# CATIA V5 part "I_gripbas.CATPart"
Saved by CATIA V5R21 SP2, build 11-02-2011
Part number: I_gripbas
Bounding box of the stored display mesh (mm): x -50 to 50, y -50 to 50, z 0 to 40
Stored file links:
  \\ariel.ad.iei.liu.se\LAB_DELMIA\A1_LAB_INTRO_2011\LAB_INTRO_DATA_2011\I_gripbas.CATPart
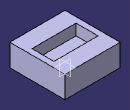
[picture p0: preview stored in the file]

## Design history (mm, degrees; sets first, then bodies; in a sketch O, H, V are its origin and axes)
Body1 (main body)
  Sketch1 on xy-plane, origin (0, 0, 0), H (1, 0, 0), V (0, 1, 0)
    line L1 (-50, -50) -> (50, -50)
    line L2 (50, -50) -> (50, 50)
    line L3 (50, 50) -> (-50, 50)
    line L4 (-50, 50) -> (-50, -50)
    horizontal: L1 H, L3 H
    vertical: L2 V, L4 V
  Pad1: profile Sketch1, direction (0, 0, 1), length 40
  Sketch2 on xy-plane, origin (0, 0, 0), H (1, 0, 0), V (0, 1, 0)
    line L1 (-40, 20) -> (40, 20)
    line L2 (40, 20) -> (40, -20)
    line L3 (40, -20) -> (-40, -20)
    line L4 (-40, -20) -> (-40, 20)
    horizontal: L1 H, L3 H
    vertical: L2 V, L4 V
  Pocket1: profile Sketch2, direction (0, 0, 1), length 40, opposite side length -20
